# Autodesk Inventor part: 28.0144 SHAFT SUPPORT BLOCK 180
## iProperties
Created: 2007-06
Part Number: 28.0144 SHAFT SUPPORT BLOCK 180
Material: Aluminum-6061
Document SubType Name: Modeling
Designer: Andy Moles
Density: 2.71 g/cm^3
Author: Andy Moles
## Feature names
1. Extrusion1
2. Extrusion2
